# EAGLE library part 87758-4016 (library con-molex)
40 Pin - 2mm Dual Row Single Wafer, Vertical T/H HDR Source: http://www.molex.com/pdm_docs/sd/877580616_sd.pdf
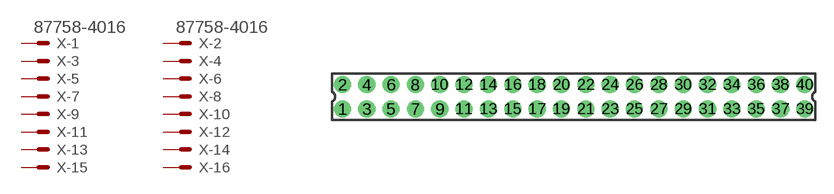
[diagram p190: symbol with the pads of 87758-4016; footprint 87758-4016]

Designator prefix X; gates -1=MV -2=MV -3=M -4=M -5=M -6=M -7=M -8=M -9=M -10=M -11=M -12=M -13=M -14=M -15=M -16=M -17=M -18=M -19=M -20=M -21=M -22=M -23=M -24=M -25=M -26=M -27=M -28=M -29=M -30=M -31=M -32=M -33=M -34=M -35=M -36=M -37=M -38=M -39=M -40=M

## 87758-4016 (MPN: 87758-4016; OC_FARNELL: unknown; OC_NEWARK: 25M5691)  [87758-4016]
1  -1:S  pas
2  -2:S  pas
3  -3:S  pas
4  -4:S  pas
5  -5:S  pas
6  -6:S  pas
7  -7:S  pas
8  -8:S  pas
9  -9:S  pas
10  -10:S  pas
11  -11:S  pas
12  -12:S  pas
13  -13:S  pas
14  -14:S  pas
15  -15:S  pas
16  -16:S  pas
17  -17:S  pas
18  -18:S  pas
19  -19:S  pas
20  -20:S  pas
21  -21:S  pas
22  -22:S  pas
23  -23:S  pas
24  -24:S  pas
25  -25:S  pas
26  -26:S  pas
27  -27:S  pas
28  -28:S  pas
29  -29:S  pas
30  -30:S  pas
31  -31:S  pas
32  -32:S  pas
33  -33:S  pas
34  -34:S  pas
35  -35:S  pas
36  -36:S  pas
37  -37:S  pas
38  -38:S  pas
39  -39:S  pas
40  -40:S  pas

## Footprint 87758-4016 (pad centres in mm)
40 Pin - 2mm Dual Row Single Wafer, Vertical T/H HDR Source: http://www.molex.com/pdm_docs/sd/877580616_sd.pdf
drill 0.9 pad 1.27 round: 1 -19,-1; 2 -19,1; 3 -17,-1; 4 -17,1; 5 -15,-1; 6 -15,1; 7 -13,-1; 8 -13,1; 9 -11,-1; 10 -11,1; 11 -9,-1; 12 -9,1; 13 -7,-1; 14 -7,1; 15 -5,-1; 16 -5,1; 17 -3,-1; 18 -3,1; 19 -1,-1; 20 -1,1; 21 1,-1; 22 1,1; 23 3,-1; 24 3,1; 25 5,-1; 26 5,1; 27 7,-1; 28 7,1; 29 9,-1; 30 9,1; 31 11,-1; 32 11,1; 33 13,-1; 34 13,1; 35 15,-1; 36 15,1; 37 17,-1; 38 17,1; 39 19,-1; 40 19,1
